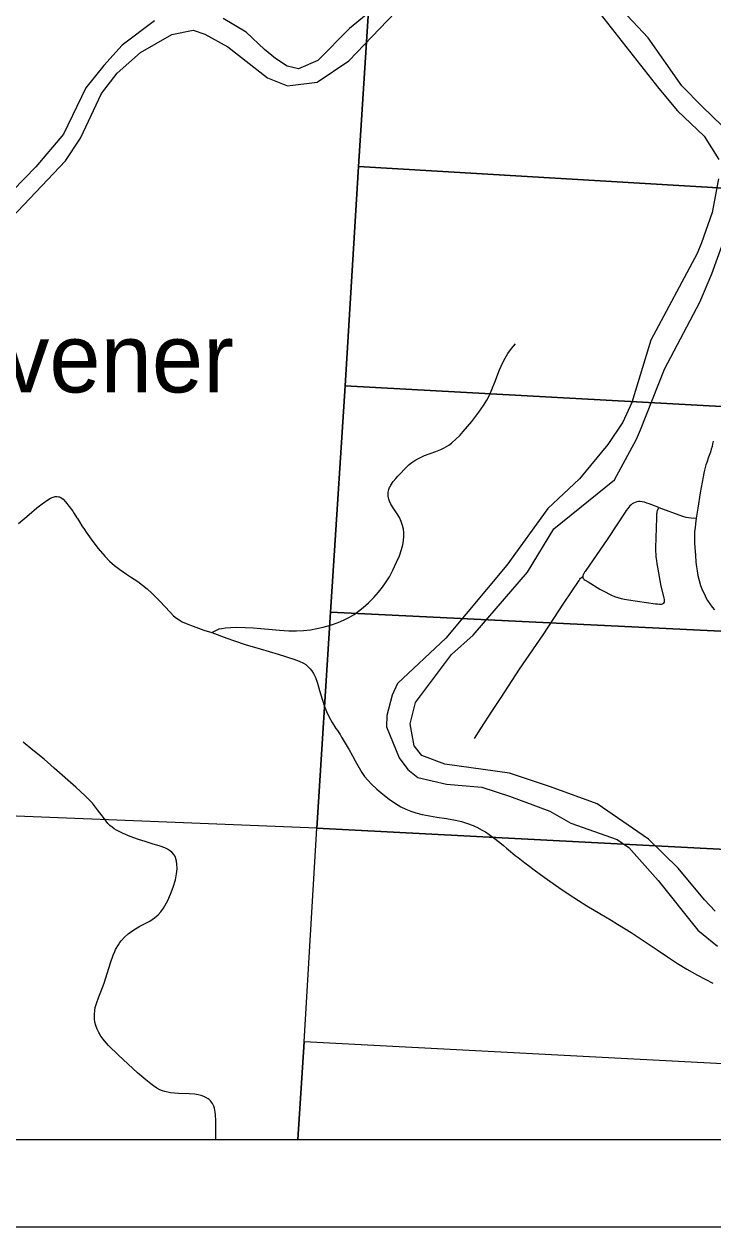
# Model space of a CAD drawing. Extents: x 21.4 to 65.3, y 4 to 26.
# Drawn here: x 25.873 to 26.662, y 17.954 to 19.331 of the extents above; entities that cross this region are included whole.
import ezdxf

# ---------------------------------------------------------------- set-up
doc = ezdxf.new("R2010")
doc.units = 0
for name, color, linetype in [('Default', 7, 'Continuous'), ('GM_X_County_Road', 7, 'Continuous'), ('GM_X_Major_River', 7, 'Continuous'), ('GM_X_Section', 7, 'Continuous'), ('GM_X_Township_Road', 7, 'Continuous'), ('GM_X_Unincorporated_Text', 7, 'Continuous'), ('SH_Cut_Line', 7, 'Continuous'), ('SH_Data', 7, 'Continuous')]:
    doc.layers.add(name, color=color, linetype=linetype)

msp = doc.modelspace()

# ---------------------------------------------------------------- linework, layer by layer
at = {"layer": 'Default'}
for points in [[(25.1262, 18.0542), (26.1864, 18.0542), (26.1936, 18.1661), (26.208, 18.4108), (25.1472, 18.4529)], [(26.1864, 18.0542), (27.2217, 18.0542), (27.2253, 18.1117), (26.1936, 18.1661)]]:
    msp.add_lwpolyline(points, close=True, dxfattribs=at)
msp.add_lwpolyline([(25.1151, 18.0542), (28.6177, 18.0542)], dxfattribs=at)
at = {"layer": 'GM_X_County_Road'}
for points in [[(26.6619, 18.8535), (26.6614, 18.8507), (26.6608, 18.8476), (26.6599, 18.8444), (26.6588, 18.841), (26.6568, 18.8352), (26.6547, 18.8294), (26.6538, 18.8266), (26.6529, 18.8237), (26.6522, 18.8205), (26.6515, 18.8169), (26.6507, 18.8128), (26.6473, 18.7944), (26.6443, 18.7769), (26.6426, 18.7654), (26.6416, 18.7589), (26.6412, 18.7545), (26.6408, 18.7502), (26.6407, 18.7462), (26.6407, 18.7421), (26.6407, 18.7373), (26.641, 18.7315), (26.6416, 18.723), (26.6422, 18.7153), (26.6429, 18.7097), (26.6436, 18.7052), (26.6446, 18.7), (26.646, 18.6942), (26.6476, 18.6884), (26.6498, 18.6829), (26.652, 18.6785), (26.6538, 18.6749), (26.6557, 18.6714), (26.6582, 18.6674), (26.6609, 18.6636), (26.6634, 18.6605)], [(25.8661, 18.7594), (25.8783, 18.7698), (25.8873, 18.7774), (25.8932, 18.782), (25.8998, 18.7866), (25.903, 18.7885), (25.9058, 18.7897), (25.9082, 18.7903), (25.9101, 18.7903), (25.9119, 18.7901), (25.913, 18.7898), (25.9147, 18.7891), (25.9173, 18.7874), (25.9202, 18.7842), (25.9283, 18.7734), (25.9301, 18.7709), (25.9332, 18.7659)], [(25.9332, 18.7659), (25.9337, 18.7651), (25.936, 18.7614), (25.9389, 18.7567), (25.9418, 18.7527), (25.9438, 18.7495), (25.9513, 18.7389), (25.9573, 18.7309), (25.965, 18.722), (25.9706, 18.7162), (25.9762, 18.7113), (25.9822, 18.7068), (25.9899, 18.7016), (25.9945, 18.6985), (26.0028, 18.6931), (26.0083, 18.689), (26.0135, 18.6846), (26.019, 18.6796), (26.0281, 18.6704), (26.0398, 18.6578), (26.0437, 18.6539), (26.0471, 18.6512), (26.0501, 18.6491), (26.0538, 18.647), (26.0583, 18.6449), (26.0664, 18.6418), (26.0786, 18.6374), (26.0877, 18.6347), (26.1048, 18.6283), (26.1136, 18.6251), (26.126, 18.621), (26.1432, 18.6158), (26.1635, 18.6099), (26.1818, 18.604), (26.1876, 18.6018), (26.1927, 18.5995), (26.1953, 18.5979), (26.1977, 18.5959), (26.2003, 18.5932), (26.2022, 18.5908), (26.2041, 18.5876), (26.2063, 18.5831), (26.2087, 18.5767), (26.2112, 18.5684), (26.214, 18.5582), (26.2168, 18.55), (26.2191, 18.5442), (26.2217, 18.5386), (26.2256, 18.5316), (26.2299, 18.5248), (26.2315, 18.5223), (26.2346, 18.5178), (26.2364, 18.5148), (26.2371, 18.5138), (26.2394, 18.51), (26.2428, 18.5043), (26.2439, 18.5024), (26.2446, 18.5011), (26.249, 18.4933), (26.2519, 18.4879), (26.2563, 18.4797), (26.2595, 18.4745), (26.2627, 18.4699), (26.2663, 18.4656), (26.2706, 18.4612), (26.2769, 18.4552), (26.2836, 18.4496), (26.2909, 18.4439), (26.298, 18.439), (26.3044, 18.4351), (26.3098, 18.4323), (26.3155, 18.43), (26.3214, 18.4282), (26.3285, 18.4264), (26.337, 18.4248), (26.3456, 18.4234), (26.3566, 18.4216), (26.367, 18.4197), (26.3736, 18.4182), (26.3784, 18.4168), (26.3819, 18.4156), (26.3848, 18.4145), (26.387, 18.4136), (26.3893, 18.4126), (26.3914, 18.4117), (26.3974, 18.4085), (26.4011, 18.4063), (26.4053, 18.4036), (26.4113, 18.3992), (26.4176, 18.3942), (26.4218, 18.3907), (26.4251, 18.3878), (26.4298, 18.3838), (26.4351, 18.3795), (26.4386, 18.3769), (26.4464, 18.3708), (26.4519, 18.3668), (26.4569, 18.3631), (26.4685, 18.3547), (26.4852, 18.3429), (26.496, 18.3356), (26.5079, 18.3277), (26.5174, 18.3218), (26.5323, 18.3129), (26.5452, 18.3053), (26.5526, 18.3008), (26.5679, 18.2913), (26.582, 18.2822), (26.5979, 18.2713), (26.6097, 18.2633), (26.6211, 18.2558), (26.6318, 18.2494), (26.6442, 18.2424), (26.6618, 18.2331)], [(26.0921, 18.0542), (26.0924, 18.0657), (26.0922, 18.0753), (26.092, 18.083), (26.0917, 18.0857), (26.0913, 18.0878), (26.0908, 18.09), (26.09, 18.0923), (26.0884, 18.0955), (26.0862, 18.0984), (26.0848, 18.0999), (26.0835, 18.1008), (26.081, 18.1023), (26.0784, 18.1035), (26.0754, 18.1045), (26.0721, 18.1054), (26.0681, 18.106), (26.0618, 18.1064), (26.0494, 18.1069), (26.0451, 18.1072), (26.0402, 18.1077), (26.0337, 18.1091), (26.0311, 18.11), (26.0282, 18.1112), (26.0245, 18.1131), (26.0207, 18.1157), (26.0178, 18.1178), (26.0119, 18.1226), (26.0025, 18.1307), (25.9808, 18.1509), (25.9695, 18.1619), (25.9647, 18.1671), (25.9605, 18.1727), (25.9582, 18.1767), (25.9563, 18.1805), (25.9547, 18.1847), (25.9538, 18.1884), (25.9532, 18.1925), (25.9531, 18.1975), (25.9535, 18.2018), (25.9542, 18.2055), (25.9554, 18.2098), (25.9582, 18.2176), (25.9606, 18.2234), (25.9643, 18.2334), (25.9718, 18.2565), (25.9748, 18.2654), (25.9764, 18.2694), (25.9775, 18.2717), (25.9806, 18.2771), (25.9822, 18.2797), (25.9838, 18.2818), (25.9876, 18.2859), (25.9919, 18.2897), (25.9973, 18.2936), (26.0053, 18.2984), (26.0165, 18.3042), (26.0221, 18.308), (26.0264, 18.3115), (26.0292, 18.3147), (26.0323, 18.3192), (26.0371, 18.3279), (26.0405, 18.3352), (26.0435, 18.3433), (26.0459, 18.3516), (26.0473, 18.3583), (26.0478, 18.3642), (26.0477, 18.3695), (26.0473, 18.3729), (26.046, 18.3769), (26.0452, 18.3788), (26.0442, 18.3804), (26.0419, 18.3832), (26.0393, 18.3852), (26.0368, 18.3868), (26.0337, 18.3882), (26.0284, 18.3902), (26.0192, 18.3928), (26.0114, 18.3953), (26.0035, 18.3978), (25.9942, 18.4013), (25.9852, 18.4051), (25.9786, 18.4084), (25.9758, 18.41), (25.9735, 18.4117), (25.9708, 18.4138), (25.9687, 18.416), (25.9647, 18.4212), (25.9569, 18.4316), (25.9509, 18.4391), (25.9427, 18.4475), (25.9318, 18.4576), (25.9071, 18.4792), (25.8955, 18.4896), (25.8827, 18.5), (25.8716, 18.5093)]]:
    msp.add_lwpolyline(points, dxfattribs=at)
at = {"layer": 'GM_X_Major_River'}
for points in [[(25.8449, 19.0958), (25.9201, 19.1747), (25.9374, 19.2006), (25.9613, 19.2516), (25.9793, 19.2749), (26.006, 19.2985), (26.0419, 19.3192), (26.0664, 19.3243), (26.0797, 19.3198), (26.1062, 19.3052), (26.1514, 19.2698), (26.1742, 19.2604), (26.2082, 19.2648), (26.2447, 19.2889), (26.3331, 19.382)], [(26.6839, 19.2035), (26.6493, 19.2367), (26.6261, 19.2604), (26.5876, 19.3156), (26.5336, 19.373)], [(26.2837, 19.3574), (26.2453, 19.3261), (26.2092, 19.2895), (26.1869, 19.2799), (26.1741, 19.2828), (26.1608, 19.2919), (26.1482, 19.302), (26.1269, 19.322), (26.1008, 19.3374)], [(26.5284, 19.3483), (26.5997, 19.2576), (26.621, 19.232), (26.6518, 19.2029), (26.6686, 19.1761)], [(26.0221, 19.3347), (25.9848, 19.3071), (25.9638, 19.2839), (25.9435, 19.2583), (25.9177, 19.2051), (25.8861, 19.1677), (25.8199, 19.1002)], [(26.6683, 19.1541), (26.6609, 19.1154), (26.6487, 19.0808), (26.6438, 19.0686), (26.5906, 18.9693), (26.5687, 18.8978), (26.5586, 18.8754), (26.5414, 18.8499), (26.5087, 18.8106), (26.4726, 18.7766), (26.4256, 18.7118), (26.3557, 18.628), (26.3004, 18.5761), (26.2941, 18.5631), (26.2881, 18.5396), (26.2878, 18.5267), (26.3024, 18.4911), (26.3123, 18.4779), (26.3237, 18.4688), (26.3566, 18.4611), (26.3971, 18.4575), (26.4286, 18.4474), (26.4748, 18.4303), (26.4991, 18.4164), (26.5521, 18.3977), (26.5654, 18.3887), (26.5989, 18.3506), (26.6446, 18.2939), (26.667, 18.2755)], [(26.6642, 18.3157), (26.652, 18.3285), (26.6219, 18.3647), (26.5881, 18.3979), (26.5292, 18.4385), (26.4758, 18.458), (26.4288, 18.4736), (26.3546, 18.4838), (26.3281, 18.4939), (26.3193, 18.5048), (26.315, 18.5302), (26.321, 18.5545), (26.3623, 18.6094), (26.3871, 18.6316), (26.4495, 18.7036), (26.4795, 18.7535), (26.5488, 18.8093), (26.5742, 18.8561), (26.5787, 18.8668), (26.6063, 18.936), (26.6468, 19.0128), (26.6606, 19.0452), (26.6885, 19.1223)]]:
    msp.add_lwpolyline(points, dxfattribs=at)
at = {"layer": 'GM_X_Section'}
for points in [[(25.208, 19.459), (26.2708, 19.4063), (26.2556, 19.168), (26.2403, 18.9172), (26.2238, 18.6579), (26.208, 18.4108), (25.1472, 18.4529)], [(26.2711, 19.4096), (27.3079, 19.3538), (27.2925, 19.1065), (26.2556, 19.168), (26.2708, 19.4063)], [(27.2925, 19.1065), (27.2763, 18.86), (26.2403, 18.9172), (26.2556, 19.168)], [(26.2403, 18.9172), (27.2763, 18.86), (27.2592, 18.6074), (26.2238, 18.6579)], [(27.2592, 18.6074), (27.2401, 18.3567), (26.208, 18.4108), (26.2238, 18.6579)], [(27.2401, 18.3567), (27.2253, 18.1117), (26.1936, 18.1661), (26.208, 18.4108)]]:
    msp.add_lwpolyline(points, close=True, dxfattribs=at)
at = {"layer": 'GM_X_Township_Road'}
for points in [[(26.0877, 18.6347), (26.0922, 18.6368), (26.0938, 18.6377), (26.096, 18.6387), (26.099, 18.6394), (26.1033, 18.64), (26.1095, 18.6404), (26.1164, 18.6406), (26.1257, 18.6405), (26.1356, 18.6399), (26.1653, 18.6372), (26.1758, 18.6365), (26.1845, 18.6365), (26.1926, 18.6369), (26.2006, 18.6378), (26.2079, 18.6391), (26.2152, 18.6408), (26.2236, 18.6432), (26.2324, 18.6462), (26.2393, 18.6491), (26.2454, 18.6521), (26.2507, 18.6553), (26.2557, 18.6589), (26.2611, 18.6632), (26.2671, 18.6686), (26.2733, 18.6747), (26.2786, 18.6807), (26.2833, 18.6866), (26.2868, 18.6916), (26.2911, 18.6985), (26.2952, 18.7062), (26.2994, 18.7152), (26.3026, 18.7226), (26.305, 18.7297), (26.3064, 18.7351), (26.3073, 18.74), (26.3077, 18.7449), (26.3076, 18.7493), (26.3072, 18.753), (26.3063, 18.7572), (26.3046, 18.7619), (26.3025, 18.7664), (26.3, 18.7706), (26.2955, 18.7774), (26.2929, 18.7817), (26.2912, 18.7849), (26.2905, 18.7873), (26.29, 18.789), (26.2898, 18.7908), (26.2896, 18.7921), (26.2896, 18.7934), (26.2898, 18.7952), (26.2906, 18.7982), (26.2914, 18.8005), (26.2922, 18.8023), (26.2928, 18.8034), (26.2956, 18.8075), (26.2983, 18.8109), (26.3007, 18.8137), (26.3033, 18.8164), (26.3087, 18.8222), (26.3136, 18.8268), (26.3169, 18.8294), (26.3215, 18.8324), (26.3258, 18.8348), (26.3315, 18.8372), (26.3379, 18.8395), (26.3443, 18.8418), (26.3501, 18.8441), (26.354, 18.8459), (26.3593, 18.8491), (26.3623, 18.8513), (26.3632, 18.8521), (26.3673, 18.8559), (26.3717, 18.8603), (26.3758, 18.8649), (26.3806, 18.8706), (26.3854, 18.8763), (26.3877, 18.8792), (26.3937, 18.887), (26.3991, 18.8947), (26.4026, 18.9005), (26.4058, 18.9065), (26.4086, 18.9128), (26.412, 18.9214), (26.4174, 18.9352), (26.4212, 18.9437), (26.4237, 18.9487), (26.4269, 18.954), (26.4309, 18.9596), (26.4356, 18.965)], [(26.5998, 18.7777), (26.5919, 18.7808), (26.5888, 18.782), (26.5861, 18.7829), (26.5832, 18.7838), (26.5807, 18.7842), (26.5783, 18.7845), (26.5765, 18.7845), (26.5745, 18.7841), (26.5727, 18.7835), (26.5709, 18.7828), (26.5694, 18.7819), (26.568, 18.7809), (26.5666, 18.7796), (26.5653, 18.7782), (26.5641, 18.7767), (26.5623, 18.7742), (26.5611, 18.7724), (26.5414, 18.7424), (26.5152, 18.7045), (26.5147, 18.7037), (26.5142, 18.703), (26.5137, 18.702), (26.5132, 18.701), (26.5129, 18.7004), (26.5127, 18.6996), (26.5126, 18.6987)], [(26.5987, 18.7093), (26.5979, 18.7133), (26.5974, 18.7169), (26.5969, 18.7212), (26.5966, 18.7244), (26.5965, 18.7275), (26.5965, 18.7315), (26.5973, 18.7658), (26.5974, 18.7676), (26.5975, 18.7691), (26.5976, 18.7704), (26.5978, 18.7717), (26.598, 18.7729), (26.5984, 18.7742), (26.5998, 18.7777), (26.6268, 18.7678), (26.6306, 18.7668), (26.6338, 18.7662), (26.6368, 18.7659), (26.6426, 18.7654)], [(26.6064, 18.6711), (26.6063, 18.6722), (26.6059, 18.6744), (26.6026, 18.6876), (26.5987, 18.7093)], [(26.3885, 18.5134), (26.3959, 18.5247), (26.4094, 18.5455), (26.4191, 18.5602), (26.4403, 18.5925), (26.4671, 18.6321), (26.4911, 18.6681), (26.5084, 18.6942), (26.5093, 18.6956), (26.5101, 18.6967), (26.5111, 18.6976), (26.5126, 18.6987)], [(26.5126, 18.6987), (26.5127, 18.6973), (26.5132, 18.6963), (26.5141, 18.6955), (26.5153, 18.6947), (26.5188, 18.6925), (26.5323, 18.6842), (26.5353, 18.6826), (26.5389, 18.6807), (26.5425, 18.6789), (26.5456, 18.6774), (26.549, 18.676), (26.5527, 18.6747), (26.5567, 18.6736), (26.5605, 18.6729), (26.565, 18.6722), (26.596, 18.6675), (26.5983, 18.6673), (26.6005, 18.6671), (26.6016, 18.667), (26.6028, 18.6672), (26.6041, 18.6674), (26.6049, 18.6678), (26.6055, 18.6683), (26.6061, 18.6692), (26.6064, 18.6701), (26.6064, 18.6711)]]:
    msp.add_lwpolyline(points, dxfattribs=at)
at = {"layer": 'SH_Cut_Line'}
msp.add_lwpolyline([(23.5473, 18.0542), (28.6177, 18.0542)], dxfattribs=at)
at = {"layer": 'SH_Data'}
for p, q in [((23.5473, 18.0542), (30.3473, 18.0542)), ((23.4473, 17.9542), (30.4473, 17.9542))]:
    msp.add_line(p, q, dxfattribs=at)

# ---------------------------------------------------------------- texts
at = {"layer": 'GM_X_Unincorporated_Text'}
msp.add_text('Thivener', height=0.07898, rotation=0, dxfattribs=at).set_placement((25.702, 18.9095))

doc.saveas('drawing.dxf')
